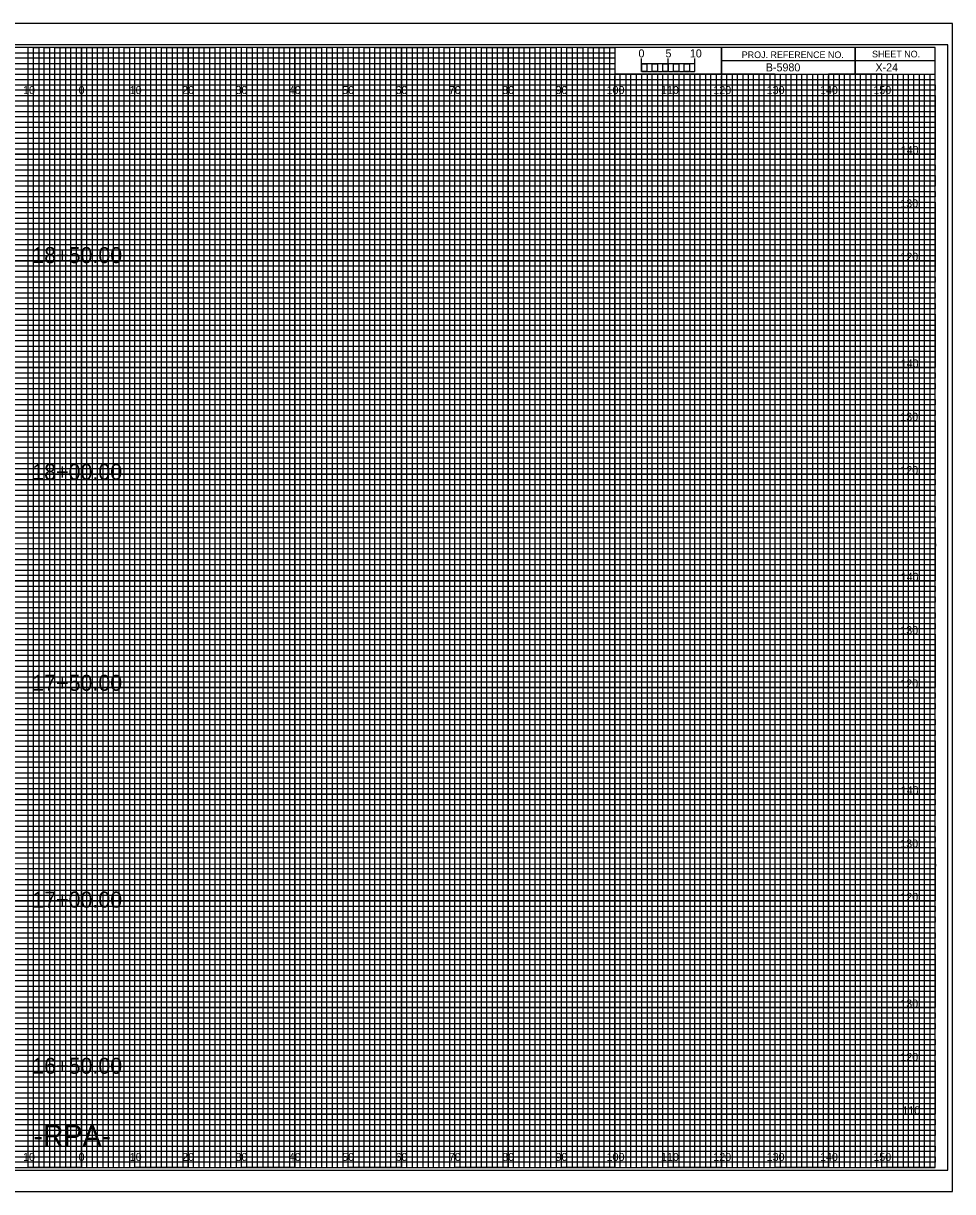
# Model space of a CAD drawing. Extents: x -13 to 323, y -5 to 1974.
# Drawn here: x 149.1 to 323.3, y -4.5 to 214.5 of the extents above; entities that cross this region are included whole.
import ezdxf

# ---------------------------------------------------------------- set-up
doc = ezdxf.new("R2010")
doc.units = 0
for name, color, linetype in [('Exist Cross Section Cell', 7, 'Continuous'), ('Exist XS Center Line Elevation Label', 7, 'Continuous'), ('Exist XS Ground Line', 7, 'Continuous'), ('Prop CMT Bridge Girder Bottom Critical Point Inside', 7, 'Continuous'), ('Prop CMT Guardrail Graphics', 7, 'Continuous'), ('Prop CMT Guardrail Widen Shoulder', 7, 'Continuous'), ('Prop CMT Pvmt Course 1', 7, 'Continuous'), ('Prop CMT Pvmt Course 2', 7, 'Continuous'), ('Prop CMT Pvmt Course 3', 7, 'Continuous'), ('Prop CMT Pvmt Surface', 7, 'Continuous'), ('Prop CMT Pvmt Surface Shoulder', 7, 'Continuous'), ('Prop CMT Shld Paved Course 1', 7, 'Continuous'), ('Prop CMT Shld Paved Course 2', 7, 'Continuous'), ('Prop CMT Shld Paved Course 3', 7, 'Continuous'), ('Prop CMT Slope Grass', 7, 'Continuous'), ('Prop CMT Subgrade Earthwork', 7, 'Continuous'), ('Scratch_Level_1', 7, 'Continuous')]:
    doc.layers.add(name, color=color, linetype=linetype)

msp = doc.modelspace()

# ---------------------------------------------------------------- linework, layer by layer
at = {"layer": 'Exist XS Center Line Elevation Label'}
for points in [[(145, 0), (155, 0), (155, 210), (165, 210), (165, 0), (175, 0), (175, 210), (185, 210), (185, 0), (195, 0), (195, 210), (205, 210), (205, 0), (215, 0), (215, 210), (225, 210), (225, 0), (235, 0), (235, 210), (245, 210), (245, 0), (255, 0), (255, 210), (259.93, 210), (260, 210), (260, 205), (264.99, 205), (264.99, 0), (275, 0), (275, 205), (285, 205), (285, 0), (295, 0), (295, 205), (305, 205), (305, 0), (315, 0), (315, 205)], [(0, 205), (275, 205)], [(0, 185), (320, 185), (320, 195), (0, 195)], [(0, 165), (320, 165), (320, 175), (0, 175)], [(0, 145), (320, 145), (320, 155), (0, 155)], [(0, 125), (320, 125), (320, 135), (0, 135)], [(0, 105), (320, 105), (320, 115), (0, 115)], [(0, 85), (320, 85), (320, 95), (0, 95)], [(0, 65), (320, 65), (320, 75), (0, 75)], [(0, 45), (320, 45), (320, 55), (0, 55)], [(0, 25), (320, 25), (320, 35), (0, 35)], [(0, 5), (320, 5), (320, 15), (0, 15)]]:
    msp.add_lwpolyline(points, dxfattribs=at)
at = {"layer": 'Exist XS Ground Line'}
for p, q in [((150, 210), (140, 210)), ((150, 0), (150, 210)), ((170, 210), (160, 210)), ((160, 210), (160, 0)), ((170, 0), (170, 210)), ((190, 210), (180, 210)), ((180, 210), (180, 0)), ((190, 0), (190, 210)), ((210, 210), (200, 210)), ((200, 210), (200, 0)), ((210, 0), (210, 210)), ((230, 210), (220, 210)), ((220, 210), (220, 0)), ((230, 0), (230, 210)), ((250, 210), (240, 210)), ((240, 210), (240, 0)), ((250, 0), (250, 210)), ((260, 210), (260, 0)), ((270, 0), (270, 205)), ((290, 205), (280, 205)), ((280, 205), (280, 0)), ((290, 0), (290, 205)), ((310, 205), (300, 205)), ((300, 205), (300, 0)), ((310, 0), (310, 205)), ((160, 0), (150, 0)), ((180, 0), (170, 0)), ((200, 0), (190, 0)), ((220, 0), (210, 0)), ((240, 0), (230, 0)), ((260, 0), (250, 0)), ((280, 0), (270, 0)), ((300, 0), (290, 0)), ((320, 0), (310, 0)), ((320, 0), (320, 0))]:
    msp.add_line(p, q, dxfattribs=at)
for points in [[(0, 200), (320, 200), (320, 190), (0, 190)], [(0, 180), (320, 180), (320, 170), (0, 170)], [(0, 160), (320, 160), (320, 150), (0, 150)], [(0, 140), (320, 140), (320, 130), (0, 130)], [(0, 120), (320, 120), (320, 110), (0, 110)], [(0, 100), (320, 100), (320, 90), (0, 90)], [(0, 80), (320, 80), (320, 70), (0, 70)], [(0, 60), (320, 60), (320, 50), (0, 50)], [(0, 40), (320, 40), (320, 30), (0, 30)], [(0, 20), (320, 20), (320, 10), (0, 10)]]:
    msp.add_lwpolyline(points, dxfattribs=at)
at = {"layer": 'Prop CMT Pvmt Course 2'}
for p, q in [((265, 205.49), (265, 207.9)), ((265, 206.9), (265, 207.9)), ((270, 205.49), (270, 207.9)), ((275, 205.49), (275, 207.9)), ((275, 206.9), (275, 207.9))]:
    msp.add_line(p, q, dxfattribs=at)
for points in [[(275, 206.9), (265, 206.9), (265, 205.49), (275, 205.49)], [(265, 206.9), (266, 206.9), (266, 205.49), (265, 205.49)], [(267, 206.9), (268, 206.9), (268, 205.49), (267, 205.49)], [(269, 206.9), (270, 206.9), (270, 205.49), (269, 205.49)], [(271, 206.9), (272, 206.9), (272, 205.49), (271, 205.49)], [(273, 206.9), (274, 206.9), (274, 205.49), (273, 205.49)]]:
    msp.add_lwpolyline(points, close=True, dxfattribs=at)
at = {"layer": 'Prop CMT Pvmt Course 3'}
msp.add_lwpolyline([(-13.4, -4.5), (323.3, -4.5), (323.3, 214.5), (-13.4, 214.5)], close=True, dxfattribs=at)
at = {"layer": 'Prop CMT Pvmt Surface'}
for p, q in [((150, 0), (150, 210)), ((160, 0), (160, 210)), ((170, 0), (170, 210)), ((180, 0), (180, 210)), ((190, 0), (190, 210)), ((200, 0), (200, 210)), ((210, 0), (210, 210)), ((220, 0), (220, 210)), ((230, 0), (230, 210)), ((240, 0), (240, 210)), ((250, 0), (250, 210)), ((260, 0), (260, 204.69)), ((270, 0), (270, 204.69)), ((280, 0), (280, 204.69)), ((290, 0), (290, 204.69)), ((300, 0), (300, 204.69)), ((310, 0), (310, 204.69)), ((0, 200), (320, 200)), ((0, 190), (320, 190)), ((0, 180), (320, 180)), ((0, 170), (320, 170)), ((0, 160), (320, 160)), ((0, 150), (320, 150)), ((0, 140), (320, 140)), ((0, 130), (320, 130)), ((0, 120), (320, 120)), ((0, 110), (320, 110)), ((0, 100), (320, 100)), ((0, 90), (320, 90)), ((0, 80), (320, 80)), ((0, 70), (320, 70)), ((0, 60), (320, 60)), ((0, 50), (320, 50)), ((0, 40), (320, 40)), ((0, 30), (320, 30)), ((0, 20), (320, 20)), ((0, 10), (320, 10))]:
    msp.add_line(p, q, dxfattribs=at)
at = {"layer": 'Prop CMT Pvmt Surface Shoulder'}
for p, q in [((323.3, 214.5), (-13.4, 214.5)), ((-13.4, -4.5), (323.3, -4.5))]:
    msp.add_line(p, q, dxfattribs=at)
at = {"layer": 'Prop CMT Shld Paved Course 1'}
for p, q in [((0, 209), (260, 209)), ((260, 209), (260, 207.98)), ((260, 207.98), (0, 207.98)), ((0, 207), (260, 207)), ((260, 205.89), (0, 205.89)), ((260, 207), (260, 205.89)), ((0, 204), (320, 204))]:
    msp.add_line(p, q, dxfattribs=at)
for points in [[(0, 203), (270, 203), (320, 203), (320, 202), (0, 202)], [(0, 201), (320, 201), (320, 199), (0, 199)], [(0, 198), (320, 198), (320, 197), (0, 196.98)], [(0, 196), (320, 196), (320, 194), (0, 194)], [(0, 193), (320, 193), (320, 192), (0, 192)], [(0, 191), (320, 191), (320, 189), (0, 189)], [(0, 188), (320, 188), (320, 187), (0, 187)], [(0, 186), (320, 186), (320, 184), (0, 184)], [(0, 183), (320, 183), (320, 182), (0, 182)], [(0, 181), (320, 181), (320, 179), (0, 179)], [(0, 178), (320, 178), (320, 177), (0, 177)], [(0, 176), (320, 176), (320, 173.95), (320, 173), (320, 172), (0, 172)], [(0, 174), (320, 174), (320, 173), (0, 173)], [(0, 171), (320, 171), (320, 169), (0, 169.03)], [(0, 169.03), (320, 169), (320, 168), (0, 168)], [(0, 167), (320, 167), (320, 166), (0, 166)], [(0, 164), (320, 164), (320, 163), (0, 163)], [(0, 162), (320, 162), (320, 161), (0, 161)], [(-0.07, 158.89), (320, 158.89), (320, 157.88), (-0.07, 157.88)], [(0, 157), (320, 157), (320, 156), (0, 156)], [(0, 154), (320, 154), (320, 153), (0, 153)], [(0, 152), (320, 152), (320, 151), (0, 151)], [(0, 149), (320, 149), (320, 148), (0, 148)], [(0, 147), (320, 147), (320, 146), (0, 146)], [(0, 144), (320, 144), (320, 143), (0, 143)], [(0, 142), (320, 142), (320, 141), (0, 141)], [(0, 139), (320, 139), (319.99, 137.98), (0, 138)], [(0, 137), (320, 137), (320, 136), (0, 136)], [(0, 134), (320, 134), (320, 133), (0, 133)], [(0, 132), (320, 132), (320, 131), (0, 131)], [(0, 129), (320, 129), (320, 128), (0, 128)], [(0, 127), (320, 127), (320, 126), (0, 126)], [(0, 124), (320, 124), (320, 123), (0, 123)], [(0, 122), (320, 122), (320, 121), (0, 121)], [(0, 119), (320, 119), (320, 118), (0, 118)], [(0, 116.99), (320.07, 116.91), (320, 116), (0, 116)], [(0, 114), (320, 114), (320, 113), (0, 113)], [(0, 112), (320, 112), (320, 111), (0, 111)], [(0, 109), (320, 109), (320, 108), (0, 108)], [(0, 107), (320, 107), (320, 106), (0, 106)], [(0, 104), (320, 104), (320, 103), (0, 103)], [(0, 102), (320, 102), (320, 101), (0, 101)], [(0, 99), (320, 99), (320, 98), (0, 98)], [(0, 97), (320, 97), (320, 96), (0, 96)], [(0, 94), (320, 94), (320, 93), (0, 93)], [(0, 92), (320, 92), (320, 91), (0, 91)], [(0, 89), (320, 89), (320, 88), (0, 88)], [(0, 87), (320, 87), (320, 86), (0, 86)], [(0, 84), (320, 84), (320, 83), (0, 83)], [(0, 82), (320, 82), (320, 81), (0, 81)], [(0, 79), (320, 79), (319.99, 77.98), (0, 78)], [(0, 77), (320, 77), (320, 76), (0, 76)], [(0, 74), (320, 74), (320, 73), (0, 73)], [(0, 72), (320, 72), (320, 71), (0, 71)], [(0, 69), (320, 69), (320, 68), (0, 68)], [(0, 67), (320, 67), (320, 66), (0, 66)], [(0, 64), (320, 64), (320, 63), (0, 63)], [(0, 62), (320, 62), (320, 61), (0, 61)], [(0, 59), (320, 59), (320, 58), (0, 58)], [(0, 56.99), (320.07, 56.91), (320, 56), (0, 56)], [(0, 54), (320, 54), (320, 53), (0, 53)], [(0, 52), (320, 52), (320, 51), (0, 51)], [(0, 49), (320, 49), (320, 48), (0, 48)], [(0, 47), (320, 47), (320, 46), (0, 46)], [(0, 44), (320, 44), (320, 43), (0, 43)], [(0, 42), (320, 42), (320, 41), (0, 41)], [(0, 39), (320, 39), (320, 38), (0, 38)], [(0, 37), (320, 37), (320, 36), (0, 36)], [(0, 34), (320, 34), (320, 33), (0, 33)], [(0, 32), (320, 32), (320, 31), (0, 31)], [(0, 29), (320, 29), (320, 28), (0, 28)], [(0, 27), (320, 27), (320, 26), (0, 26)], [(0, 24), (320, 24), (320, 23), (0, 23)], [(0, 22), (320, 22), (320, 21), (0, 21)], [(0, 19), (320, 19), (320, 18), (0, 18)], [(0, 17), (320, 17), (320, 16), (0, 16)], [(0, 14), (320, 14), (320, 13), (0, 13)], [(0, 12), (320, 12), (320, 11), (0, 11)], [(0, 9), (320, 9), (320, 8), (0, 8)], [(0, 7), (320, 7), (320, 6), (0, 6)], [(0, 4), (320, 4), (320, 3), (0, 3)], [(0, 2), (320, 2), (320, 1), (0, 1)]]:
    msp.add_lwpolyline(points, dxfattribs=at)
at = {"layer": 'Prop CMT Shld Paved Course 2'}
for p, q in [((305, 210), (305, 205)), ((305, 205), (305, 210)), ((280, 207.5), (280, 205)), ((320, 207.49), (280, 207.49)), ((280, 205), (320, 205))]:
    msp.add_line(p, q, dxfattribs=at)
for points in [[(320, 210), (0, 210), (0, 0), (320, 0)], [(280, 210), (260, 210), (260, 205.03), (280, 205.03)], [(320, 210), (280, 210), (280, 205), (320, 205)]]:
    msp.add_lwpolyline(points, close=True, dxfattribs=at)
at = {"layer": 'Prop CMT Shld Paved Course 3'}
for p, q in [((267, 205), (266.01, 205)), ((266.01, 205), (266.01, 0)), ((267, 0), (267, 205)), ((269, 205), (268, 205)), ((268, 205), (268, 0)), ((269, 0), (269, 205)), ((266.01, 0), (265, 0)), ((268, 0), (267, 0))]:
    msp.add_line(p, q, dxfattribs=at)
for points in [[(150, 0), (151, 0), (151, 210), (152, 210), (152, 0)], [(152, 0), (153, 0), (153, 210), (154, 210), (154, 0)], [(155, 0), (156, 0), (156, 210), (157, 210), (157, 0)], [(157, 0), (158, 0), (158, 210), (159, 210), (159, 0)], [(160, 0), (161, 0), (161, 210), (162, 210), (162, 0)], [(162, 0), (163, 0), (163, 210), (164, 210), (164, 0)], [(165, 0), (166, 0), (166, 210), (167, 210), (167, 0)], [(167, 0), (168, 0), (168, 210), (169, 210), (169, 0)], [(170, 0), (171, 0), (171, 210), (172, 210), (172, 0)], [(172, 0), (173, 0), (173, 210), (174, 210), (174, 0)], [(175, 0), (176, 0), (176, 210), (177, 210), (177, 0)], [(177, 0), (178, 0), (178, 210), (179, 210), (179, 0)], [(180, 0), (181, 0), (181, 210), (182, 210), (182, 0)], [(182, 0), (183, 0), (183, 210), (184, 210), (184, 0)], [(185, 0), (186, 0), (186, 210), (187, 210), (187, 0)], [(187, 0), (188, 0), (188, 210), (189, 210), (189, 0)], [(190, 0), (191, 0), (191, 210), (192, 210), (192, 0)], [(192, 0), (193, 0), (193, 210), (194, 210), (194, 0)], [(195, 0), (196, 0), (196, 210), (197, 210), (197, 0)], [(197, 0), (198, 0), (198, 210), (199, 210), (199, 0)], [(200, 0), (201, 0), (201, 210), (202, 210), (202, 0)], [(202, 0), (203, 0), (203, 210), (204, 210), (204, 0)], [(205, 0), (206, 0), (206, 210), (207, 210), (207, 0)], [(207, 0), (208, 0), (208, 210), (209, 210), (209, 0)], [(210, 0), (211, 0), (211, 210), (212, 210), (212, 0)], [(212, 0), (213, 0), (213, 210), (214, 210), (214, 0)], [(215, 0), (216, 0), (216, 210), (217, 210), (217, 0)], [(217, 0), (218, 0), (218, 210), (219, 210), (219, 0)], [(220, 0), (221, 0), (221, 210), (222, 210), (222, 0)], [(222, 0), (223, 0), (223, 210), (224, 210), (224, 0)], [(225, 0), (226, 0), (226, 210), (227, 210), (227, 0)], [(227, 0), (228, 0), (228, 210), (229, 210), (229, 0)], [(230, 0), (231, 0), (231, 210), (232, 210), (232, 0)], [(232, 0), (233, 0), (233, 210), (234, 210), (234, 0)], [(235, 0), (236, 0), (236, 210), (237, 210), (237, 0)], [(237, 0), (238, 0), (238, 210), (239, 210), (239, 0)], [(240, 0), (241, 0), (241, 210), (242, 210), (242, 0)], [(242, 0), (243, 0), (243, 210), (244, 210), (244, 0)], [(245, 0), (246, 0), (246, 210), (247, 210), (247, 0)], [(247, 0), (248, 0), (248, 210), (249, 210), (249, 0)], [(250, 0), (251, 0), (251, 210), (252, 210), (252, 0)], [(252, 0), (253, 0), (253, 210), (254, 210), (254, 0)], [(255, 0), (256, 0), (256, 210), (257, 210), (257, 0)], [(257, 0), (258, 0), (258, 210), (259, 210), (259, 0)], [(260, 0), (261, 0), (261, 205), (262.02, 205), (262.02, 0)], [(262, 0), (263, 0), (263, 205), (263.99, 205), (263.99, 0)], [(270, 0), (270.98, 0), (270.98, 205), (272, 205), (272, 0)], [(272, 0), (273, 0), (273, 205), (274.05, 205), (274.05, 0)], [(275, 0), (276, 0), (276, 205), (277, 205), (277, 0)], [(277, 0), (278, 0), (278, 205), (279, 205), (279, 0)], [(280, 0), (281, 0), (281, 205), (282, 205), (282, 0)], [(282, 0), (283, 0), (283, 205), (284, 205), (284, 0)], [(285, 0), (286, 0), (286, 205), (287, 205), (287, 0)], [(287, 0), (288, 0), (288, 205), (289, 205), (289, 0)], [(290, 0), (291, 0), (291, 205), (292, 205), (292, 0)], [(292, 0), (293, 0), (293, 205), (294, 205), (294, 0)], [(295, 0), (296, 0), (296, 205), (297, 205), (297, 0)], [(297, 0), (298, 0), (298, 205), (299, 205), (299, 0)], [(300, 0), (301, 0), (301, 205), (302, 205), (302, 0)], [(302, 0), (303, 0), (303, 205), (304, 205), (304, 0)], [(305, 0), (306, 0), (306, 205), (307, 205), (307, 0)], [(307, 0), (308, 0), (308, 205), (309, 205), (309, 0)], [(310, 0), (311, 0), (311, 205), (312, 205), (312, 0)], [(312, 0), (313, 0), (313, 205), (314, 205), (314, 0)], [(315, 0), (316, 0), (316, 205), (317, 205), (317, 0)], [(317, 0), (318, 0), (318, 205), (319, 205), (319, 0)]]:
    msp.add_lwpolyline(points, dxfattribs=at)
at = {"layer": 'Prop CMT Subgrade Earthwork'}
msp.add_lwpolyline([(-10.8, -0.5), (322.4, -0.5), (322.4, 210.5), (-10.8, 210.5)], close=True, dxfattribs=at)

# ---------------------------------------------------------------- texts
at = {"layer": 'Exist Cross Section Cell'}
for s, p in [('10', (149.04, 201.25)), ('0', (159.45, 201.25)), ('0', (159.45, 201.25)), ('10', (169.04, 201.25)), ('20', (178.86, 201.25)), ('30', (188.86, 201.25)), ('40', (198.86, 201.25)), ('50', (208.86, 201.25)), ('60', (218.86, 201.25)), ('70', (228.86, 201.25)), ('80', (238.86, 201.25)), ('90', (248.86, 201.25)), ('100', (258.44, 201.25)), ('110', (268.62, 201.25)), ('120', (278.44, 201.25)), ('130', (288.44, 201.25)), ('140', (298.44, 201.25)), ('150', (308.44, 201.25)), ('10', (149.04, 1.25)), ('0', (159.45, 1.25)), ('0', (159.45, 1.25)), ('10', (169.04, 1.25)), ('20', (178.86, 1.25)), ('30', (188.86, 1.25)), ('40', (198.86, 1.25)), ('50', (208.86, 1.25)), ('60', (218.86, 1.25)), ('70', (228.86, 1.25)), ('80', (238.86, 1.25)), ('90', (248.86, 1.25)), ('100', (258.44, 1.25)), ('110', (268.62, 1.25)), ('120', (278.44, 1.25)), ('130', (288.44, 1.25)), ('140', (298.44, 1.25)), ('150', (308.44, 1.25))]:
    msp.add_text(s, height=1.5, dxfattribs=at).set_placement(p)
at = {"layer": 'Prop CMT Bridge Girder Bottom Critical Point Inside'}
for s, p in [('5', (269.47, 208.12)), ('10', (274.04, 208.12))]:
    msp.add_text(s, height=1.5, dxfattribs=at).set_placement(p)
at = {"layer": 'Prop CMT Guardrail Graphics'}
msp.add_text('B-5980', height=1.5, dxfattribs=at).set_placement((288.28, 205.5))
at = {"layer": 'Prop CMT Guardrail Widen Shoulder'}
msp.add_text('X-24', height=1.5, dxfattribs=at).set_placement((308.83, 205.5))
at = {"layer": 'Prop CMT Pvmt Course 1'}
for s, p in [('140', (313.57, 190)), ('130', (313.49, 180)), ('120', (313.5, 170)), ('140', (313.57, 150)), ('130', (313.49, 140)), ('120', (313.5, 130)), ('140', (313.57, 110)), ('130', (313.49, 100)), ('120', (313.5, 90)), ('140', (313.57, 70)), ('130', (313.49, 60)), ('120', (313.5, 50)), ('130', (313.49, 30)), ('120', (313.5, 20)), ('110', (313.88, 10))]:
    msp.add_text(s, height=1.5, dxfattribs=at).set_placement(p)
at = {"layer": 'Prop CMT Pvmt Course 2'}
msp.add_text('0', height=1.5, dxfattribs=at).set_placement((264.41, 208.12))
at = {"layer": 'Prop CMT Shld Paved Course 2'}
for s, p in [('PROJ. REFERENCE NO.', (283.77, 207.99)), ('SHEET NO.', (308.19, 208.12))]:
    msp.add_text(s, height=1.25, dxfattribs=at).set_placement(p)
at = {"layer": 'Prop CMT Slope Grass'}
for s, p in [('18+50.00', (150.77, 169.56)), ('18+00.00', (150.77, 128.93)), ('17+50.00', (150.77, 89.38)), ('17+00.00', (150.77, 48.74)), ('16+50.00', (150.77, 17.59))]:
    msp.add_text(s, height=3, dxfattribs=at).set_placement(p)
at = {"layer": 'Scratch_Level_1'}
msp.add_text('-RPA-', height=4, dxfattribs=at).set_placement((150.97, 4))

doc.saveas('drawing.dxf')
